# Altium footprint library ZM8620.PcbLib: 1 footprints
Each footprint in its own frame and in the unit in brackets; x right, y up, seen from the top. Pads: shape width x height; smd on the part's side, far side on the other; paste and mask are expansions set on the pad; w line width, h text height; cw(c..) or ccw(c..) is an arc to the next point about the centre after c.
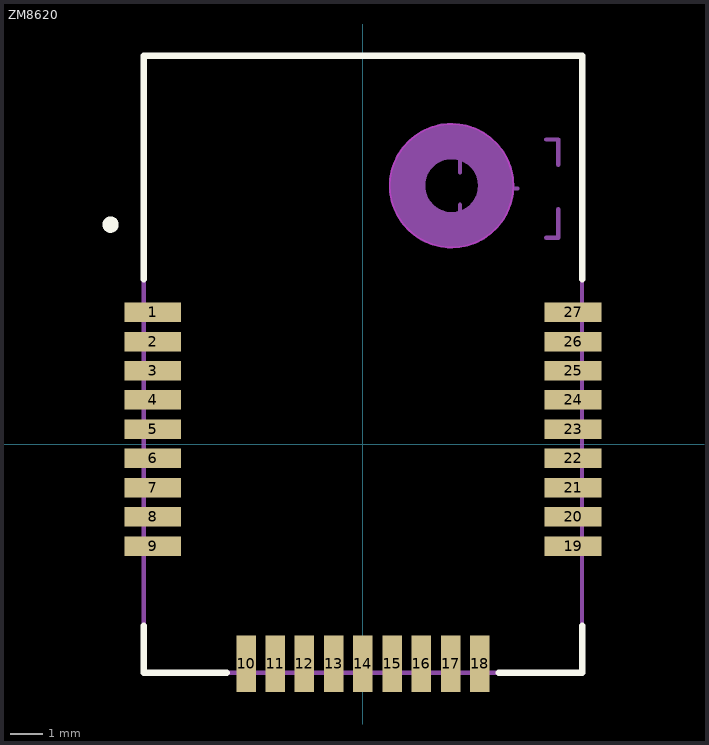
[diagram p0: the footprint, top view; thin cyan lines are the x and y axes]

## ZM8620 [mm] "ZLGLIB"
height 0.635
pads (28):
  rect 1.75x0.6 smd: 1(-6.475,4.062) 2(-6.475,3.163) 3(-6.475,2.262) 4(-6.475,1.363) 5(-6.475,0.463) 6(-6.475,-0.438) 7(-6.475,-1.337) 8(-6.475,-2.238) 9(-6.475,-3.137) 19(6.475,-3.137) 20(6.475,-2.238) 21(6.475,-1.337) 22(6.475,-0.438) 23(6.475,0.463) 24(6.475,1.362) 25(6.475,2.262) 26(6.475,3.162) 27(6.475,4.062)
  rect 0.6x1.75 smd: 10(-3.6,-6.762) 11(-2.7,-6.762) 12(-1.8,-6.762) 13(-0.9,-6.762) 14(0,-6.762) 15(0.9,-6.762) 16(1.8,-6.762) 17(2.7,-6.762) 18(3.6,-6.762)
  rect 0.6x1.05 on Mech15 paste-0.5 mask+0.051: ""(-3.6,-6.512)
Top Layer keep-out:
  circle w0.05: c2.731,7.963 r1.9
Top Overlay:
  circle w0.25: c-7.772,6.763 r0.127
  lines w0.2: -6.75,-5.588 -6.75,-7.038 -4.191,-7.038 ; -6.75,5.08 -6.75,11.963 6.75,11.963 6.75,5.08 ; 4.191,-7.038 6.75,-7.038 6.75,-5.588
Mechanical 15:
  circle w1.118: c2.731,7.963 r1.372
  circle w0.838: c2.731,7.963 r1.46
  lines w0.127: 2.989,7.375 2.989,6.359 3.258,6.359 ; 2.989,8.37 2.989,9.386 3.258,9.386 ; 4.248,7.872 4.756,7.872 ; 4.502,7.618 4.502,8.126 ; 5.645,6.359 6.016,6.359 6.016,7.237 ; 5.645,9.386 6.016,9.386 6.016,8.609 ; -6.75,-7.038 6.75,-7.038 6.75,11.963 -6.75,11.963 -6.75,-7.038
